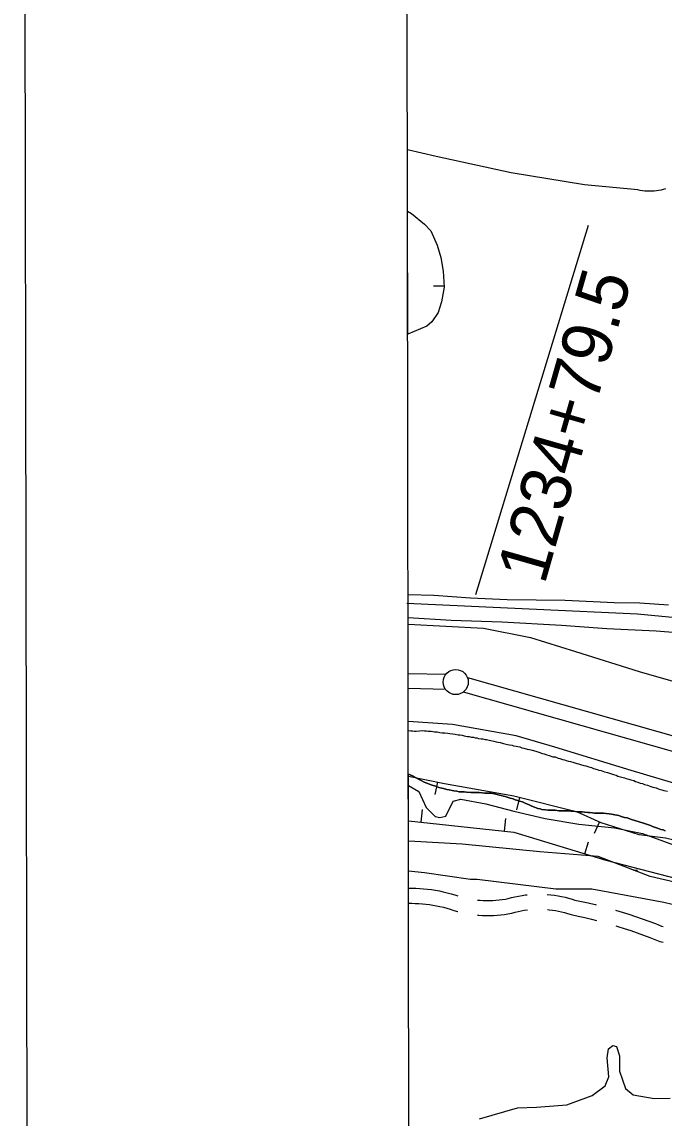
# Model space of a CAD drawing. Extents: x 3329332 to 3367211, y 631066 to 656469.
# Drawn here: x 3332666 to 3333945, y 649922 to 652105 of the extents above; entities that cross this region are included whole.
import ezdxf

# ---------------------------------------------------------------- set-up
doc = ezdxf.new("R2010")
doc.units = 0
for name, color, linetype in [('V-ANNO-SYMB', 7, 'Continuous'), ('V-BORW-LINE', 7, 'Continuous'), ('V-GRID-FRAM', 7, 'Continuous'), ('V-LEVE-TOET', 7, 'Continuous'), ('V-ROAD-CNTR', 7, 'Continuous'), ('V-SITE-VEGE', 7, 'Continuous'), ('V-SURV-IDEN', 7, 'Continuous'), ('V-SURV-LINE', 7, 'Continuous'), ('V-TOPO-SHOR', 7, 'Continuous'), ('V-WETL-SWMP', 7, 'Continuous')]:
    doc.layers.add(name, color=color, linetype=linetype)

msp = doc.modelspace()

# ---------------------------------------------------------------- linework, layer by layer
at = {"layer": 'V-ANNO-SYMB'}
msp.add_lwpolyline([(3332709.6, 632280), (3365792.7, 632342.5), (3365749.4, 655259), (3332666.3, 655196.5), (3332709.6, 632280)], dxfattribs=at)
at = {"layer": 'V-BORW-LINE'}
for p, q in [((3333493.5, 650590.6), (3333488.5, 650566.1)), ((3333657.2, 650560.1), (3333651.1, 650535.9)), ((3333461.2, 650511.4), (3333463.9, 650536.2)), ((3333626.9, 650493.4), (3333629.6, 650518.2)), ((3333816.1, 650511.6), (3333805.9, 650488.8)), ((3333786.9, 650448.1), (3333794.2, 650472))]:
    msp.add_line(p, q, dxfattribs=at)
for points in [[(3333895.4, 650486.2), (3333819.6, 650510.1), (3333772.5, 650531), (3333645.6, 650563), (3333507.6, 650587.8), (3333435.8, 650602.2)], [(3333435.9, 650514.1), (3333645.9, 650491.3), (3333828.8, 650435.2), (3334020.8, 650385.4), (3334185.6, 650374.2), (3334178.2, 650396.3), (3334075.8, 650436.7), (3334030.5, 650459.4), (3333947.5, 650479.1), (3333895.4, 650486.2)]]:
    msp.add_lwpolyline(points, dxfattribs=at)
at = {"layer": 'V-GRID-FRAM'}
msp.add_lwpolyline([(3333429.9, 654632), (3364987.9, 654691.7), (3365030.2, 636507.7), (3333456.4, 636448), (3333429.9, 654632)], dxfattribs=at)
at = {"layer": 'V-LEVE-TOET'}
for points in [[(3333435.4, 650905.5), (3333585.5, 650897.7), (3333679, 650879.4), (3333768.5, 650850.9), (3333895.5, 650811.2), (3334038.8, 650770.5), (3334147.6, 650739.9), (3334262.4, 650708.4), (3334325.5, 650698.2), (3334402.7, 650693.1), (3334513.5, 650701.2), (3334625.3, 650703.1), (3334696.5, 650699.1), (3334786, 650683.8), (3334902.8, 650653.2), (3335067.5, 650597.3), (3335296.2, 650516.9), (3335501.5, 650447.7), (3335722.1, 650366.3), (3335912.8, 650298.1)], [(3335689.5, 650195.5), (3335557.3, 650237.2), (3335440.4, 650276.9), (3335322.5, 650312.5), (3335215.8, 650348.2), (3335081.7, 650394), (3334972.9, 650433.6), (3334854, 650479.4), (3334779.8, 650503.9), (3334726.9, 650512), (3334672, 650515.1), (3334472.8, 650518.2), (3334320.3, 650517.2), (3334251.2, 650520.3), (3334164.8, 650534.6), (3334046.9, 650564.1), (3333879.2, 650614), (3333727.7, 650660.8), (3333650.5, 650683.2), (3333523.4, 650705.6), (3333435.6, 650711.6)]]:
    msp.add_lwpolyline(points, dxfattribs=at)
at = {"layer": 'V-ROAD-CNTR'}
for points in [[(3333925.2, 651768.4), (3333920.6, 651768.1), (3333915.9, 651768), (3333911.2, 651768.1), (3333906.6, 651768.4), (3333902, 651769), (3333897.4, 651769.7), (3333892.8, 651770.7), (3333786.2, 651781), (3333640.5, 651804.9), (3333491.1, 651837.4), (3333434, 651850.4)], [(3333948, 651773), (3333943.5, 651771.7), (3333939, 651770.5), (3333934.4, 651769.6), (3333929.8, 651768.9), (3333925.2, 651768.4)], [(3333432.9, 650947.5), (3333447, 650946.9), (3333691.2, 650935.8), (3333892.3, 650926.5), (3334030.9, 650913.2), (3334142.9, 650900.9), (3334255.1, 650884), (3334366.4, 650860.9), (3334439.5, 650842.9), (3334514.4, 650823.8), (3334602.1, 650797.5), (3334727.3, 650759.4), (3335017.7, 650656.7), (3335451.3, 650502.7), (3335830.6, 650371.5)], [(3333436, 650379.5), (3333442.5, 650379.6), (3333450.4, 650379.4), (3333458.3, 650379.1), (3333466.2, 650378.5), (3333474.1, 650377.8), (3333482, 650376.8), (3333489.8, 650375.6), (3333497.6, 650374.2), (3333505.3, 650372.5), (3333513, 650370.7), (3333520.7, 650368.6), (3333528.3, 650366.4), (3333534.3, 650364.4)], [(3333573.4, 650356.1), (3333578.6, 650355.6), (3333584.9, 650355.2), (3333591.2, 650355), (3333597.5, 650355), (3333603.8, 650355.2), (3333610.1, 650355.6), (3333616.4, 650356.2), (3333622.7, 650357), (3333628.9, 650358.1), (3333634.7, 650359.2), (3333640.9, 650360.9), (3333647.9, 650362.6), (3333655, 650364), (3333662.1, 650365.2), (3333669.2, 650366.2), (3333672.3, 650366.6)], [(3333712.2, 650367.3), (3333712.3, 650367.3), (3333719.5, 650366.6), (3333726.7, 650365.7), (3333733.8, 650364.6), (3333740.9, 650363.3), (3333747.9, 650361.7), (3333754.9, 650359.9), (3333761.8, 650357.9), (3333767.6, 650356), (3333780.3, 650353.4), (3333794, 650350.3), (3333807.6, 650347.1), (3333809.9, 650346.5)], [(3333436.3, 650349.5), (3333442.4, 650349.6), (3333449.5, 650349.4), (3333456.6, 650349.1), (3333463.7, 650348.7), (3333470.8, 650348), (3333477.8, 650347.1), (3333484.8, 650346), (3333491.8, 650344.7), (3333498.7, 650343.3), (3333505.6, 650341.6), (3333512.5, 650339.8), (3333519.3, 650337.7), (3333526.5, 650335.4), (3333533.4, 650333.3), (3333534.4, 650333.1)], [(3333573.7, 650326), (3333576.3, 650325.7), (3333583.5, 650325.3), (3333590.8, 650325), (3333598, 650325), (3333605.3, 650325.3), (3333612.5, 650325.7), (3333619.8, 650326.4), (3333627, 650327.4), (3333634.1, 650328.5), (3333641.6, 650330), (3333648.4, 650331.8), (3333654.4, 650333.3), (3333660.5, 650334.5), (3333666.7, 650335.6), (3333672.7, 650336.4)], [(3333712.6, 650337.1), (3333716.3, 650336.8), (3333722.5, 650336), (3333728.7, 650335.1), (3333734.8, 650333.9), (3333740.9, 650332.6), (3333746.9, 650331), (3333752.9, 650329.2), (3333759.8, 650327), (3333774, 650324), (3333787.3, 650321.1), (3333800.5, 650317.9), (3333810.1, 650315.5)], [(3333848.5, 650336.1), (3333861.6, 650332.2), (3333874.9, 650327.9), (3333888.2, 650323.5), (3333901.4, 650318.9), (3333914.5, 650314.1), (3333927.6, 650309.2), (3333940.1, 650304.2), (3333942.9, 650303.2)], [(3333848.6, 650304.7), (3333852.7, 650303.5), (3333865.7, 650299.4), (3333878.5, 650295.1), (3333891.3, 650290.7), (3333904.1, 650286), (3333916.7, 650281.2), (3333929.8, 650276), (3333936.5, 650273.7), (3333943, 650271.8)]]:
    msp.add_lwpolyline(points, dxfattribs=at)
at = {"layer": 'V-SITE-VEGE'}
for p, q in [((3333436.1, 650413.5), (3333435.8, 650607.1)), ((3333435.8, 650607.1), (3333439.3, 650605.4)), ((3333439.3, 650605.4), (3333444.2, 650603.2)), ((3333444.2, 650603.2), (3333451.2, 650599.4)), ((3333451.2, 650599.4), (3333456.1, 650596.7)), ((3333456.1, 650596.7), (3333461.5, 650594)), ((3333461.5, 650594), (3333467, 650590.7)), ((3333467, 650590.7), (3333470.8, 650589.7)), ((3333470.8, 650589.7), (3333474.6, 650588)), ((3333474.6, 650588), (3333478.9, 650586.4)), ((3333478.9, 650586.4), (3333485.4, 650584.2)), ((3333485.4, 650584.2), (3333490.3, 650582.6)), ((3333490.3, 650582.6), (3333496.2, 650580.4)), ((3333496.2, 650580.4), (3333502.2, 650578.8)), ((3333502.2, 650578.8), (3333506, 650578.2)), ((3333506, 650578.2), (3333512.5, 650576.1)), ((3333512.5, 650576.1), (3333516.8, 650575.5)), ((3333516.8, 650575.5), (3333522.8, 650574.4)), ((3333522.8, 650574.4), (3333526.6, 650573.9)), ((3333526.6, 650573.9), (3333532.6, 650572.8)), ((3333532.6, 650572.8), (3333536.9, 650571.7)), ((3333536.9, 650571.7), (3333541.8, 650571.7)), ((3333541.8, 650571.7), (3333547.2, 650571.7)), ((3333547.2, 650571.7), (3333551.6, 650571.2)), ((3333551.6, 650571.2), (3333560.2, 650570.6)), ((3333560.2, 650570.6), (3333565.1, 650570.1)), ((3333565.1, 650570.1), (3333568.9, 650570.1)), ((3333568.9, 650570.1), (3333573.2, 650570.1)), ((3333573.2, 650570.1), (3333577, 650570.1)), ((3333577, 650570.1), (3333583, 650569.5)), ((3333583, 650569.5), (3333587.9, 650569)), ((3333587.9, 650569), (3333591.1, 650569)), ((3333591.1, 650569), (3333596, 650569)), ((3333596, 650569), (3333599.8, 650569)), ((3333599.8, 650569), (3333607.4, 650567.4)), ((3333607.4, 650567.4), (3333612.3, 650566.3)), ((3333612.3, 650566.3), (3333617.2, 650565.2)), ((3333617.2, 650565.2), (3333620.4, 650564.1)), ((3333620.4, 650564.1), (3333625.3, 650563)), ((3333625.3, 650563), (3333628.6, 650562.5)), ((3333628.6, 650562.5), (3333634.5, 650560.3)), ((3333634.5, 650560.3), (3333638.3, 650559.2)), ((3333638.3, 650559.2), (3333644.8, 650557.6)), ((3333644.8, 650557.6), (3333648.6, 650556)), ((3333648.6, 650556), (3333654, 650554.3)), ((3333654, 650554.3), (3333657.3, 650553.2)), ((3333657.3, 650553.2), (3333663.3, 650551.6)), ((3333663.3, 650551.6), (3333669.8, 650548.4)), ((3333669.8, 650548.4), (3333675.2, 650546.7)), ((3333675.2, 650546.7), (3333677.9, 650545.1)), ((3333677.9, 650545.1), (3333681.7, 650542.9)), ((3333681.7, 650542.9), (3333687.1, 650540.8)), ((3333687.1, 650540.8), (3333693.6, 650538.6)), ((3333693.6, 650538.6), (3333698.5, 650537.5)), ((3333698.5, 650537.5), (3333701.8, 650536.4)), ((3333701.8, 650536.4), (3333708.8, 650535.9)), ((3333708.8, 650535.9), (3333714.2, 650535.3)), ((3333714.2, 650535.3), (3333722.9, 650534.8)), ((3333722.9, 650534.8), (3333728.3, 650534.8)), ((3333728.3, 650534.8), (3333735.4, 650533.7)), ((3333735.4, 650533.7), (3333739.7, 650533.7)), ((3333739.7, 650533.7), (3333743.5, 650533.7)), ((3333743.5, 650533.7), (3333751.7, 650533.7)), ((3333751.7, 650533.7), (3333756.5, 650533.7)), ((3333756.5, 650533.7), (3333759.8, 650533.1)), ((3333759.8, 650533.1), (3333765.2, 650533.1)), ((3333765.2, 650533.1), (3333771.2, 650532.1)), ((3333771.2, 650532.1), (3333775.5, 650532.1)), ((3333775.5, 650532.1), (3333782, 650531.5)), ((3333782, 650531.5), (3333786.4, 650531)), ((3333786.4, 650531), (3333792.9, 650530.4)), ((3333792.9, 650530.4), (3333796.7, 650530.4)), ((3333796.7, 650530.4), (3333802.6, 650529.9)), ((3333802.6, 650529.9), (3333806.4, 650529.3)), ((3333806.4, 650529.3), (3333810.2, 650529.3)), ((3333810.2, 650529.3), (3333816.2, 650528.8)), ((3333816.2, 650528.8), (3333820, 650528.8)), ((3333820, 650528.8), (3333824.3, 650529.3)), ((3333824.3, 650529.3), (3333829.7, 650528.2)), ((3333829.7, 650528.2), (3333835.7, 650527.7)), ((3333835.7, 650527.7), (3333840, 650527.1)), ((3333840, 650527.1), (3333846.6, 650525.5)), ((3333846.6, 650525.5), (3333854.7, 650524.4)), ((3333854.7, 650524.4), (3333859.6, 650522.3)), ((3333859.6, 650522.3), (3333866.1, 650520.6)), ((3333866.1, 650520.6), (3333871.5, 650519.5)), ((3333871.5, 650519.5), (3333880.2, 650516.8)), ((3333880.2, 650516.8), (3333888.9, 650514.1)), ((3333888.9, 650514.1), (3333893.7, 650512.5)), ((3333893.7, 650512.5), (3333897.5, 650510.9)), ((3333897.5, 650510.9), (3333901.9, 650509.8)), ((3333901.9, 650509.8), (3333910, 650507.1)), ((3333910, 650507.1), (3333918.1, 650504.3)), ((3333918.1, 650504.3), (3333921.9, 650502.7)), ((3333921.9, 650502.7), (3333927.9, 650500.5)), ((3333927.9, 650500.5), (3333931.7, 650499.5)), ((3333931.7, 650499.5), (3333938.2, 650496.7)), ((3333938.2, 650496.7), (3333943.1, 650495.7)), ((3333943.1, 650495.7), (3333947.4, 650494)), ((3333468.2, 650410.1), (3333436.1, 650413.5)), ((3333559.6, 650397), (3333468.2, 650410.1)), ((3333572.6, 650397), (3333559.6, 650397)), ((3333729.2, 650377.4), (3333572.6, 650397)), ((3333801, 650377.4), (3333729.2, 650377.4)), ((3333944.6, 650351.3), (3333801, 650377.4)), ((3334049, 650325.2), (3333944.6, 650351.3))]:
    msp.add_line(p, q, dxfattribs=at)
at = {"layer": 'V-SURV-LINE'}
for points in [[(3333435.5, 650807.6), (3333510.6, 650805.8)], [(3333553.5, 650799.3), (3334169.1, 650624.7)], [(3333509.8, 650775.8), (3333435.6, 650777.6)], [(3334160.9, 650595.8), (3333545.3, 650770.4)]]:
    msp.add_lwpolyline(points, dxfattribs=at)
msp.add_circle((3333530.1, 650790.3), 25, dxfattribs=at)
at = {"layer": 'V-TOPO-SHOR'}
msp.add_line((3333569.9, 650964.8), (3333794.6, 651700.2), dxfattribs=at)
for points in [[(3333435.3, 650964.7), (3333486.7, 650963.3), (3333559.7, 650958), (3333632.6, 650954.6), (3333748.3, 650953.2), (3333845.8, 650948.6), (3333896.5, 650948.2), (3333953.9, 650943.9)], [(3333435.3, 650919), (3333520.9, 650913.9), (3333622.1, 650910.3), (3333740.6, 650903.6), (3333831.2, 650897), (3333929.3, 650892.5), (3334013.8, 650885.8), (3334110.1, 650875.6), (3334201.2, 650865.4), (3334285.2, 650850.8), (3334352.4, 650838.4), (3334357.8, 650837.2)], [(3333435.7, 650693.7), (3333440.4, 650693.2), (3333443.7, 650693.2), (3333448, 650692.7), (3333451.3, 650692.7), (3333457.8, 650693.2), (3333463.7, 650693.8), (3333468.1, 650693.2), (3333471.9, 650693.2), (3333475.1, 650692.7), (3333481.1, 650692.7), (3333488.1, 650691.1)], [(3333488.1, 650691.1), (3333493, 650691.1), (3333498.5, 650690), (3333503.3, 650689.4), (3333508.2, 650688.9), (3333514.2, 650688.3), (3333518.5, 650687.8), (3333524.5, 650687.2), (3333528.8, 650686.2), (3333534.8, 650685.1), (3333538, 650685.1), (3333542.9, 650684.5), (3333546.7, 650683.4), (3333550, 650682.4), (3333553.8, 650681.8), (3333557, 650681.8), (3333561.4, 650680.7), (3333565.2, 650680.7), (3333568.9, 650679.1), (3333572.2, 650679.1), (3333575.5, 650678), (3333580.9, 650677.5), (3333584.1, 650676.9), (3333588.5, 650675.8), (3333591.7, 650675.8), (3333596.6, 650674.7), (3333599.9, 650674.2), (3333605.8, 650672.6), (3333610.7, 650671.5), (3333618.8, 650669.9), (3333625.3, 650667.7), (3333632.9, 650666.1), (3333637.3, 650665), (3333642.2, 650664.4), (3333645.4, 650663.3), (3333650.3, 650662.3), (3333653.5, 650661.7), (3333657.9, 650661.2), (3333661.7, 650659.5), (3333666, 650658.5), (3333672.5, 650656.8), (3333676.9, 650655.7), (3333682.3, 650654.7), (3333689.3, 650652.5), (3333697.5, 650650.3), (3333702.3, 650648.1), (3333706.1, 650647.6), (3333711.6, 650645.4), (3333716.4, 650643.8), (3333723.5, 650641.6), (3333727.8, 650641.1), (3333734.3, 650638.9), (3333737.6, 650637.8), (3333743, 650636.2), (3333746.8, 650635.1), (3333750.1, 650634), (3333754.9, 650632.9), (3333758.7, 650631.8), (3333763.6, 650630.8), (3333771.2, 650628), (3333774.5, 650627.5), (3333778.8, 650625.9), (3333785.3, 650624.2), (3333789.1, 650623.2), (3333795.1, 650621.5), (3333800.5, 650619.9), (3333804.3, 650618.3), (3333811.9, 650616.1), (3333815.1, 650615), (3333820, 650613.9), (3333826.5, 650611.2), (3333832.5, 650610.1), (3333838.5, 650608), (3333844.4, 650606.3), (3333849.3, 650604.7), (3333853.1, 650603.1), (3333860.7, 650600.9), (3333866.1, 650599.3), (3333869.4, 650598.2), (3333874.8, 650596.6), (3333879.1, 650595.5), (3333884.5, 650594.4), (3333887.8, 650592.2), (3333892.7, 650591.1), (3333897.6, 650589), (3333901.9, 650587.9), (3333905.7, 650586.2), (3333912.2, 650584.6), (3333918.7, 650582.4), (3333922.5, 650580.8), (3333929, 650579.7), (3333935.5, 650577), (3333940.4, 650575.9), (3333944.7, 650574.3), (3333951.8, 650572.7)], [(3333840, 650527.1), (3333835.7, 650527.7), (3333829.7, 650528.2), (3333824.3, 650529.3), (3333820, 650528.8), (3333816.2, 650528.8), (3333810.2, 650529.3), (3333806.4, 650529.3), (3333802.6, 650529.9), (3333796.7, 650530.4), (3333792.9, 650530.4), (3333786.4, 650531), (3333782, 650531.5), (3333775.5, 650532.1), (3333771.2, 650532.1), (3333765.2, 650533.1), (3333759.8, 650533.1), (3333756.5, 650533.7), (3333751.7, 650533.7), (3333743.5, 650533.7), (3333739.7, 650533.7), (3333735.4, 650533.7), (3333728.3, 650534.8), (3333722.9, 650534.8), (3333714.2, 650535.3), (3333708.8, 650535.9), (3333701.8, 650536.4), (3333698.5, 650537.5), (3333693.6, 650538.6), (3333687.1, 650540.8), (3333681.7, 650542.9), (3333677.9, 650545.1), (3333675.2, 650546.7), (3333669.8, 650548.4), (3333663.3, 650551.6), (3333657.3, 650553.2), (3333654, 650554.3), (3333648.6, 650556), (3333644.8, 650557.6), (3333638.3, 650559.2), (3333634.5, 650560.3), (3333628.6, 650562.5), (3333625.3, 650563), (3333620.4, 650564.1), (3333617.2, 650565.2), (3333612.3, 650566.3), (3333607.4, 650567.4), (3333599.8, 650569), (3333596, 650569), (3333591.1, 650569), (3333587.9, 650569), (3333583, 650569.5), (3333577, 650570.1), (3333573.2, 650570.1), (3333568.9, 650570.1), (3333565.1, 650570.1), (3333560.2, 650570.6), (3333551.6, 650571.2), (3333547.2, 650571.7), (3333541.8, 650571.7), (3333536.9, 650571.7), (3333532.6, 650572.8), (3333526.6, 650573.9), (3333522.8, 650574.4), (3333516.8, 650575.5), (3333512.5, 650576.1), (3333506, 650578.2), (3333502.2, 650578.8), (3333496.2, 650580.4), (3333490.3, 650582.6), (3333485.4, 650584.2), (3333478.9, 650586.4), (3333474.6, 650588), (3333470.8, 650589.7), (3333467, 650590.7), (3333461.5, 650594), (3333456.1, 650596.7), (3333451.2, 650599.4), (3333444.2, 650603.2), (3333439.3, 650605.4), (3333435.8, 650607.1)], [(3333947.4, 650494), (3333943.1, 650495.7), (3333938.2, 650496.7), (3333931.7, 650499.5), (3333927.9, 650500.5), (3333921.9, 650502.7), (3333918.1, 650504.3), (3333910, 650507.1), (3333901.9, 650509.8), (3333897.5, 650510.9), (3333893.7, 650512.5), (3333888.9, 650514.1), (3333880.2, 650516.8), (3333871.5, 650519.5), (3333866.1, 650520.6), (3333859.6, 650522.3), (3333854.7, 650524.4), (3333846.6, 650525.5), (3333840, 650527.1)]]:
    msp.add_lwpolyline(points, dxfattribs=at)
at = {"layer": 'V-WETL-SWMP'}
for p, q in [((3333434.5, 651483.7), (3333434.2, 651728.4)), ((3333434.2, 651728.4), (3333442.2, 651723.7)), ((3333442.2, 651723.7), (3333467.8, 651702.8)), ((3333467.8, 651702.8), (3333480.7, 651689.1)), ((3333480.7, 651689.1), (3333493.3, 651660.4)), ((3333493.3, 651660.4), (3333500.7, 651636)), ((3333500.7, 651636), (3333505.4, 651608.9)), ((3333505.4, 651608.9), (3333507.4, 651576.7)), ((3333485.7, 651579.5), (3333507.2, 651579.6)), ((3333507.4, 651576.7), (3333501.9, 651547.7)), ((3333501.9, 651547.7), (3333495.2, 651526.8)), ((3333495.2, 651526.8), (3333482.6, 651508)), ((3333472.4, 651499), (3333434.7, 651483.6)), ((3333482.6, 651508), (3333472.4, 651499)), ((3333434.7, 651483.6), (3333434.5, 651483.7)), ((3333436, 650473.5), (3333435.8, 650584.2)), ((3333435.8, 650584.2), (3333456.8, 650572.1)), ((3333456.8, 650572.1), (3333471, 650540.6)), ((3333524.9, 650552.8), (3333540.2, 650556.8)), ((3333540.2, 650556.8), (3333590, 650547.7)), ((3333471, 650540.6), (3333489.3, 650522.3)), ((3333510.7, 650523.3), (3333524.9, 650552.8)), ((3333590, 650547.7), (3333645.9, 650533.4)), ((3333645.9, 650533.4), (3333707.9, 650518.2)), ((3333489.3, 650522.3), (3333498.5, 650520.3)), ((3333498.5, 650520.3), (3333510.7, 650523.3)), ((3333707.9, 650518.2), (3333775, 650506.9)), ((3333775, 650506.9), (3333846.1, 650499.8)), ((3333846.1, 650499.8), (3333902, 650488.6)), ((3333902, 650488.6), (3333985.4, 650458.1)), ((3333436.5, 650473.5), (3333436, 650473.5)), ((3333543.2, 650467.4), (3333436.5, 650473.5)), ((3333697.7, 650452.1), (3333543.2, 650467.4)), ((3333813.6, 650442.9), (3333697.7, 650452.1)), ((3333917.2, 650403.2), (3333813.6, 650442.9)), ((3333884.4, 650415.8), (3333891.9, 650415.8)), ((3334048.4, 650371.6), (3333917.2, 650403.2)), ((3333831.9, 650041.6), (3333834.5, 650059.9)), ((3333834.5, 650059.9), (3333842.9, 650066.6)), ((3333842.9, 650066.6), (3333850.2, 650064.5)), ((3333850.2, 650064.5), (3333856, 650045.7)), ((3333835, 650003.9), (3333831.9, 650041.6)), ((3333856, 650045.7), (3333855.9, 650015.4)), ((3333855.9, 650015.4), (3333867.9, 649980.8)), ((3333802, 649966.8), (3333827.7, 649985.6)), ((3333827.7, 649985.6), (3333835, 650003.9)), ((3333751.2, 649948), (3333802, 649966.8)), ((3333867.9, 649980.8), (3333883.6, 649968.3)), ((3333883.6, 649968.3), (3333925.4, 649960.4)), ((3333577.5, 649920), (3333653.4, 649942.4)), ((3333653.4, 649942.4), (3333691.1, 649943.4)), ((3333691.1, 649943.4), (3333751.2, 649948)), ((3333925.4, 649960.4), (3333956.8, 649961.4))]:
    msp.add_line(p, q, dxfattribs=at)

# ---------------------------------------------------------------- texts
at = {"layer": 'V-SURV-IDEN'}
msp.add_text('1234+79.5', height=100, rotation=74.0825, dxfattribs=at).set_placement((3333706.9, 650982.5))

doc.saveas('drawing.dxf')
